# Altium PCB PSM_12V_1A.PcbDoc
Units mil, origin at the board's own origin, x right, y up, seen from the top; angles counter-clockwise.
Board outline 1600 x 1200 mil, 2 copper layers (Top Layer, Bottom Layer), stack 62 mil thick; 36 components, 17 nets, 77 pads, 9 vias.
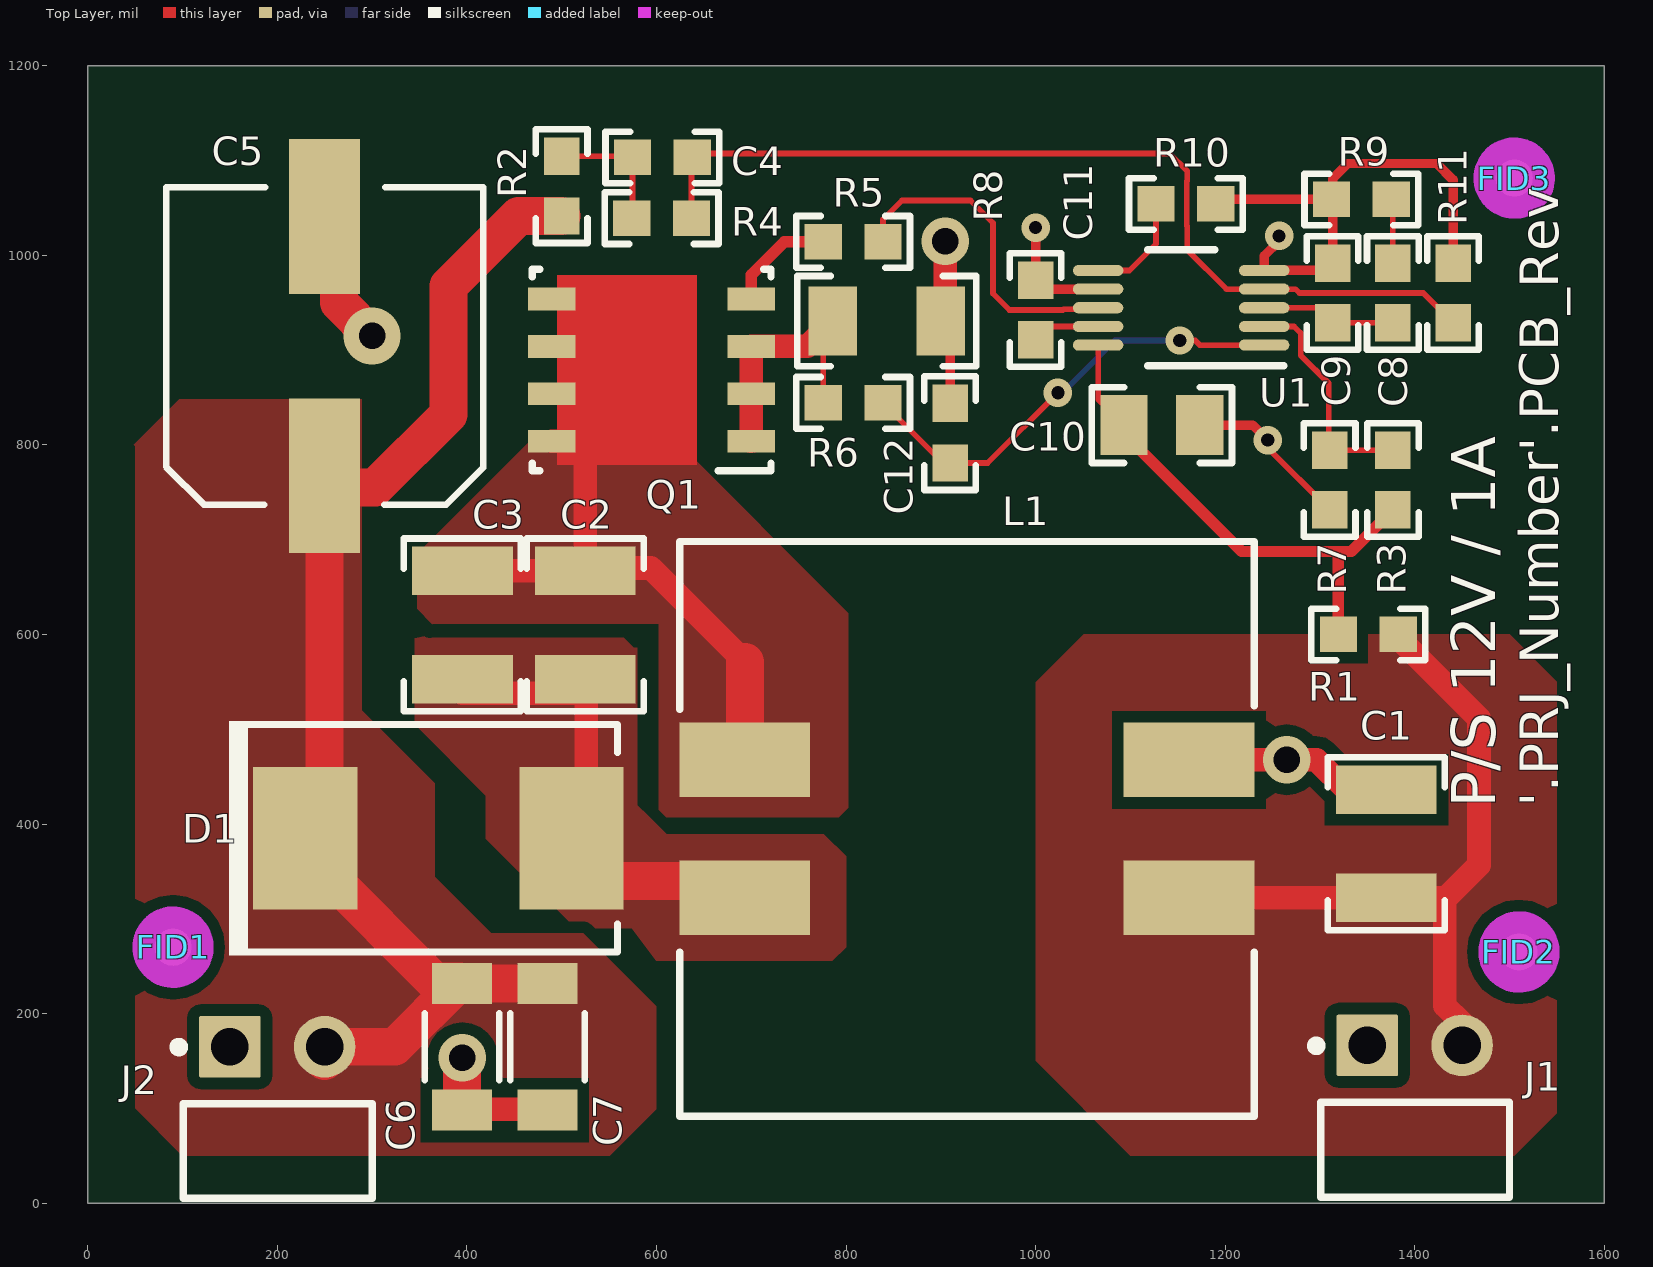
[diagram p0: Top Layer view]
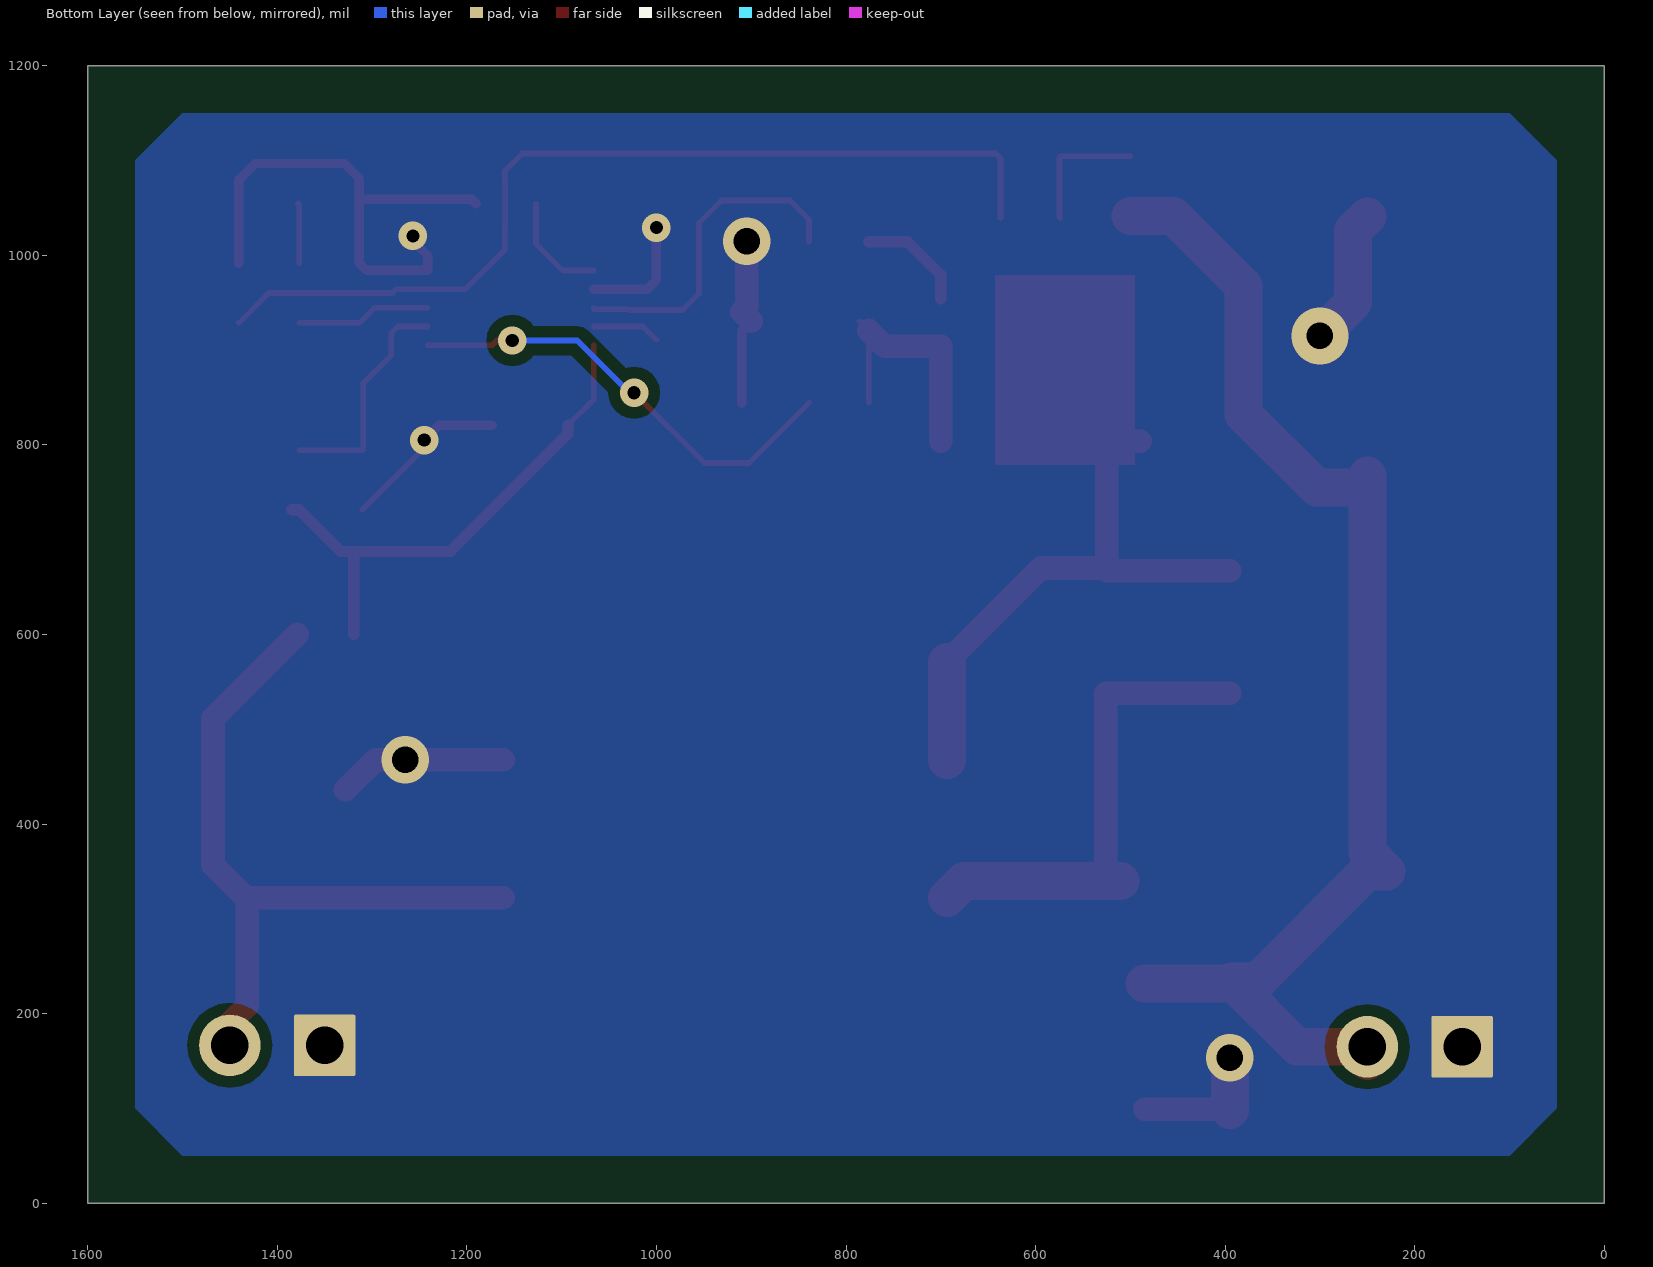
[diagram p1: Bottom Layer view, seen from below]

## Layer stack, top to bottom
Top Solder: solder mask 0.4, Solder Resist, Dk 3.5
Top Layer: signal copper 1.4
Dielectric1: core 59.2, FR-4, Dk 4.8
Bottom Layer: signal copper 1.4
Bottom Solder: solder mask 0.4, Solder Resist, Dk 3.5

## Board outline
0,0 0,1200 1600,1200 1600,0

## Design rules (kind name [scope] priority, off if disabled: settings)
AcuteAngle [All] p1: minimum=4.50000000000000E+0001 checktracksonly=FALSE
AssemblyTestPointUsage [All] p1: valid=2
BoardOutlineClearance BoardOutlineClearance_MountingHoles [OnCopper and InComponentClass('Mounting Holes')] p1: gap=39.37 ignorepadtopadclearanceinfootprint=FALSE
BoardOutlineClearance BoardOutlineClearance_Poly [OnCopper and IsPoly] p2: gap=25 ignorepadtopadclearanceinfootprint=FALSE
BoardOutlineClearance [OnCopper and Not InComponentClass('Logo') and not InComponentClass('FiducialMark') and not InRegion(1000,500,4000,800) and not InPoly] p3: gap=75 ignorepadtopadclearanceinfootprint=FALSE
Clearance Clearance_Keepouts [((IsTrack Or IsArc) And Not InPoly) And IsFree and IsKeepOut vs ((IsTrack Or IsArc) And Not InPoly) And IsFree and IsKeepOut] p1: gap=0 ignorepadtopadclearanceinfootprint=FALSE
Clearance Clearance_Poly [InPolygon] p2: gap=12 ignorepadtopadclearanceinfootprint=TRUE
Clearance Clearance_FiducialMark [IsKeepOut and InComponentClass('FiducialMark') vs IsPad and InComponentClass('FiducialMark')] p3: gap=0 ignorepadtopadclearanceinfootprint=FALSE
Clearance [All] p4: gap=7.87 ignorepadtopadclearanceinfootprint=TRUE
ComponentClearance ComponentClearance_MountingHoles_FiducialMarks [InComponentClass('Mounting Holes') vs InComponentClass('FiducialMark')] p1: gap=50 collisioncheckmode=3 verticalgap=10 showdistances=FALSE
ComponentClearance ComponentClearance_Shunt [InComponentClass('Header') vs InComponentClass('Shunt')] p2: gap=0 collisioncheckmode=3 verticalgap=0 showdistances=FALSE
ComponentClearance ComponentClearance_Logo [InComponentClass('Logo')] p3: gap=20 collisioncheckmode=3 verticalgap=10 showdistances=FALSE
ComponentClearance ComponentClearance_ScrewToNut [(HasFootprint('NY PMS 440 0025 PH')) vs (HasFootprint('Keystone_1902C'))] p4: gap=5 collisioncheckmode=3 verticalgap=10 showdistances=FALSE
ComponentClearance ComponentClearance_MountingHoles [InComponentClass('Mounting Holes')] p5: gap=250 collisioncheckmode=3 verticalgap=100000 showdistances=FALSE
ComponentClearance ComponentClearance_SmallPassives [HasFootprint('0201*') or HasFootprint('0402*') or HasFootprint('0508') or HasFootprint('0603*') or HasFootprint('0612') or HasFootprint('0805*') or HasFootprint('0815*') or HasFootprint('0830*') or HasFootprint('1206*') or HasFootprint('1210*') or HasFootprint('1808*') or HasFootprint('1812*') or HasFootprint('1825*') or HasFootprint('2010*') or HasFootprint('2220*') or HasFootprint('2225*') or HasFootprint('2512*') or HasFootprint('2728*') or HasFootprint('3518*') vs HasFootprint('0201*') or HasFootprint('0402*') or HasFootprint('0508') or HasFootprint('0603*') or HasFootprint('0612') or HasFootprint('0805*') or HasFootprint('0815*') or HasFootprint('0830*') or HasFootprint('1206*') or HasFootprint('1210*') or HasFootprint('1808*') or HasFootprint('1812*') or HasFootprint('1825*') or HasFootprint('2010*') or HasFootprint('2220*') or HasFootprint('2225*') or HasFootprint('2512*') or HasFootprint('2728*') or HasFootprint('3518*')] p6: gap=14.96 collisioncheckmode=3 verticalgap=10 showdistances=FALSE
ComponentClearance ComponentClearance_THtoSMT [IsThruComponent vs IsSMTComponent] p7: gap=40 collisioncheckmode=3 verticalgap=30 showdistances=FALSE
ComponentClearance ComponentClearance_THtoTH [IsThruComponent vs IsThruComponent] p8: gap=30 collisioncheckmode=3 verticalgap=30 showdistances=FALSE
ComponentClearance [All] p9: gap=30 collisioncheckmode=3 verticalgap=10 showdistances=FALSE
DiffPairsRouting [All] p1: maxlimit=100 minlimit=10 mostfreqgap=10 toplayer_minwidth=15 toplayer_maxwidth=15 toplayer_prefwidth=15 bottomlayer_minwidth=15 bottomlayer_maxwidth=15 bottomlayer_prefwidth=15 maxuncoupledlength=1000
FabricationTestPointUsage TestPointUsage [All] p1: valid=2 allowmultiple=FALSE
FabricationTestpoint Testpoint [All] p1: side=3 testpointundercomponent=TRUE minsize=40 maxsize=100 preferedsize=60 minholesize=0 maxholesize=40 preferedholesize=32 testpointgrid=1 allowsidetop=TRUE allowsidebottom=TRUE usegrid=TRUE gridtolerance=0.01
FanoutControl Fanout_LCC [IsLCC] p1: bgadir=Out bgaviamode=Centered fanoutstyle=Auto fanoutdirection=Alternating viagrid=1 // Fanout_LCC (Default Rule)
FanoutControl Fanout_BGA [IsBGA] p2: bgadir=Out bgaviamode=Centered fanoutstyle=Auto fanoutdirection=Alternating viagrid=1 // Fanout_BGA (Default Rule)
FanoutControl Fanout_Default [All] p4: bgadir=Out bgaviamode=Centered fanoutstyle=Auto fanoutdirection=Alternating viagrid=1 // Fanout_Default (Default Rule)
FanoutControl Fanout_Small [(CompPinCount < 5)] p5: bgadir=Out bgaviamode=Centered fanoutstyle=Auto fanoutdirection=OutThenIn viagrid=1 // Fanout_Small (Default Rule)
HoleSize [All] p1: absolutevalues=TRUE maxlimit=251 minlimit=7.87 maxpercent=80.000 minpercent=20.000
MinimumAnnularRing MinimumAnnularRing_ThermalPadVias [IsVia and InAnyComponent] p1: minimumring=5.91
MinimumAnnularRing [All] p2: minimumring=7.87
MinimumSolderMaskSliver MinimumSolderMaskSliver_Logo [InComponentClass('Logo') vs InComponentClass('Logo')] p1: minsoldermaskwidth=0.7
MinimumSolderMaskSliver [All] p2: minsoldermaskwidth=3.94
PlaneConnect [All] p1: planeconnectstyle=Relief reliefexpansion=10 reliefentries=4 reliefconductorwidth=10 reliefairgap=10
PolygonConnect [All] p1: connectstyle=Direct reliefconductorwidth=25 reliefentries=4 polygonreliefangle="90 Angle" airgapwidth=10
RoutingVias ThermalPadVias [IsVia and InAnyComponent] p1: holewidth=7.87 width=19.68 viastyle="Through Hole" minholewidth=7.87 minwidth=19.68 maxholewidth=12.99 maxwidth=23.62
RoutingVias [All] p2: holewidth=16 width=34 viastyle="Through Hole" minholewidth=7.87 minwidth=26 maxholewidth=40 maxwidth=65
SilkToBoardRegionClearance [Not ((IsComment or IsDesignator) And (Hide <> 'False')) and not InRegion(1000,500,4000,800)] p1:
SilkToSilkClearance SilkToSilkClearance_Pb-FreeLogo [(HasFootprint('Pb-Free_Overlay_Medium') OR HasFootprint('Pb-Free_Overlay_Small')) vs (HasFootprint('Pb-Free_Overlay_Medium') OR HasFootprint('Pb-Free_Overlay_Small'))] p1: silktosilkclearance=0
SilkToSilkClearance [All] p2: silktosilkclearance=3.94
SilkToSolderMaskClearance SilkToComponentPadClearance [(IsPad or IsFill or IsRegion) and InAnycomponent] p1: minsilkscreentomaskgap=5 clearancetoexposedcopper=TRUE
SilkToSolderMaskClearance "Silk to Solder Mask Opening" [All] p2: minsilkscreentomaskgap=3.94 clearancetoexposedcopper=FALSE
SolderMaskExpansion [All] p1: expansion=1.97
UnRoutedNet [All] p1: checkbadconnections=TRUE
Width [All] p1: maxlimit=100 minlimit=6 preferedwidth=10 checkconnectedcopper=TRUE
14 further rules are at their usual default settings.

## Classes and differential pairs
component class FiducialMark: FID1 FID2 FID3
component class AssemblyNote: ZZ1 ZZ2 ZZ3 ZZ4

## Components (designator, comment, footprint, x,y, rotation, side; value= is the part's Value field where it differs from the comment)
C1 "C3225X7S2A335M200AB" 1210 1370,379.12 r90 top value=3.3uF
C2 "C3225X7S2A335M200AB" 1210 524.85,609.98 r270 top value=3.3uF
C3 "C3225X7S2A335M200AB" 1210 395.27,609.98 r270 top value=3.3uF
C4 "C0603C474K8PACTU" 0603 606.27,1103.22 r0 top value=0.47uF
C5 "25SVPF180M" SVPF_E12 250,904.26 r90 top value=180uF
C6 "EMK316BB7226ML-T" 1206_190 394.8,165 r270 top value=22uF
C7 "EMK316BB7226ML-T" 1206_190 485,165 r270 top value=22uF
C8 "C1608X7R1C105K080AC" 0603 1376.97,960.17 r90 top value=1uF
C9 "C0603C474K8PACTU" 0603 1313.35,960.17 r90 top value=0.47uF
C10 "C2012X7R2A104K125AA" 0805_HV 1133.28,820.89 r0 top value=0.1uF
C11 "C1608X7R1C105K080AC" 0603 1000,942.26 r90 top value=1uF
C12 "C0603X102K5RACTU" 0603 909.84,812.39 r90 top value=1000pF
D1 "DIODE_SCHOTTKY" SMC 370,385 r0 top value=100V
FID1 "Fiducial" Fiducial10-20 90,270 r0 top
FID2 "Fiducial" Fiducial10-20 1510,265 r0 top
FID3 "Fiducial" Fiducial10-20 1505,1081.44 r0 top
J1 "TSW-102-08-G-S-RA" TSW-102-08-G-S-RA 1400,166.42 r0 top
J2 "TSW-102-08-G-S-RA" TSW-102-08-G-S-RA 200,165 r0 top
L1 "INDUCTOR_COUPLED_13_24" IND_MSD1583 927.61,394.87 r180 top value=47uH
Q1 "FDMS86101" TRANS_Fairchild_PQFN08A 594.88,878.89 r180 top value=100V
R1 "Resistor" 0603 1351,600 r0 top value=10
R2 "Resistor" 0603 500,1072.95 r270 top value=49.9
R3 "Resistor" 0603 1376.97,762.96 r270 top value=100k
R4 "Resistor" 0603 605.45,1039.16 r180 top value=49.9k
R5 "Resistor" 0603 807.48,1014.25 r180 top value=0
R6 "Resistor" 0603 807.48,844.26 r0 top value=221
R7 "Resistor" 0603 1310.34,762.96 r90 top value=33.2k
R8 "Resistor" 1206 842.91,930.44 r180 top value=0.01
R9 "Resistor" 0603 1343.67,1058.91 r0 top value=1.50k
R10 "Resistor" 0603 1158.5,1054.24 r180 top value=105k
R11 "Resistor" 0603 1440.47,960.17 r270 top value=5.90k
U1 "LM3481QMM/NOPB" DGS0010A_N 1153.6,944.59 r180 top
ZZ1 "This Assembly Note is for PCB labels only" AssemblyNoteLabel 181.93,1913 r0 top
ZZ2 "These assemblies are ESD sensitive, ESD precautions shall be observed." AssemblyNote 181.93,1804.11 r0 top
ZZ3 "These assemblies must be clean and free from flux and all contaminants. Use of no clean flux is not acceptable." AssemblyNote 181.93,1715.56 r0 top
ZZ4 "These assemblies must comply with workmanship standards IPC-A-610 Class 2, unless otherwise specified." AssemblyNote 181.93,1627 r0 top

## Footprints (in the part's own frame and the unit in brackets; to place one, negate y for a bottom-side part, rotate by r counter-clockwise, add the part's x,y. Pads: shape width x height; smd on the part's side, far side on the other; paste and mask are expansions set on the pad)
0603 [mm] "0603 from SM-752 data"
  rect 1x0.95 smd: 1(-0.8,0) 2(0.8,0)
  silkscreen extent -1.52,-0.69 1.52,0.69, body extent -0.87,-0.47 0.87,0.47, height 1
0805_HV [mil] "0805 with 30mil clearance between pads"
  rect 50x63 smd: 1(-40,0) 2(40,0)
  silkscreen extent -74,-40 74,40, body extent -43,-29 43,29, height 57
1206 [mm] "1206 from SM-752 data"
  rect 1.3x1.85 smd: 1(-1.45,0) 2(1.45,0)
  silkscreen extent -2.4,-1.21 2.4,1.21, body extent -1.7,-0.9 1.7,0.9, height 1.35
1206_190 [mm] "1206_190"
  rect 1.1x1.6 smd: 1(-1.7,0) 2(1.7,0)
  silkscreen extent -0.9,-1 0.9,1, body extent -1.75,-0.95 1.75,0.95, height 1.9
1210 [mm] "1210 from SM-752 data"
  rect 1.3x2.7 smd: 1(-1.45,0) 2(1.45,0)
  silkscreen extent -2.32,-1.57 2.32,1.57, body extent -1.7,-1.35 1.7,1.35, height 1.35
AssemblyNote [mil] "Assembly Note"
AssemblyNoteLabel [mil] "Assembly Note for PCB Labels"
DGS0010A_N [mm] "TSSOP, 10-Leads, Body 3x3mm, Pitch 0.5mm, IPC Medium Density"
  oval 1.35x0.3 smd: 1(-2.225,1) 2(-2.225,0.5) 3(-2.225,0) 4(-2.225,-0.5) 5(-2.225,-1) 6(2.225,-1) 7(2.225,-0.5) 8(2.225,0) 9(2.225,0.5) 10(2.225,1)
  silkscreen extent -2.75,-1.55 0.9,1.55, body extent -2.45,-1.5 2.45,1.5, height 0.96
Fiducial10-20 [mm]
  round 1 smd mask+0.5: 1(0,0)
  Top Layer keep-out circle w1.178: c0,0 r0.5
IND_MSD1583 [mm] "COILCRAFT"
  rect 3.5x2 smd: 1(-5.95,1.85) 2(-5.95,-1.85) 3(5.95,-1.85) 4(5.95,1.85)
  silkscreen extent -7.7,-7.7 7.7,7.7, body extent -7.55,-7.55 7.55,7.55, height 8.6
SMC [mil] "Molded Diode, 2-Leads, Body 6.9x5.8mm, IPC Medium Density, based on OnSemi component dimensions and land patterns"
  rect 110x150 smd: 1(-140.49,0) 2(140.49,0)
  silkscreen extent -221,-123 189,124, body extent -156,-116 156,116, height 91
SVPF_E12 [mm] "OS-CON  8x10"
  rect 4.15x1.9 smd: 1(-3.475,0) 2(3.475,0)
  silkscreen extent -4.25,-4.25 4.25,4.25, body extent -4.25,-4.25 4.25,4.25, height 12
TRANS_Fairchild_PQFN08A [mm] "Fairchild PQFN08A recommended land pattern"
  rect 1.27x0.61 smd: 1(-2.67,1.905) 2(-2.67,0.635) 3(-2.67,-0.635) 4(-2.67,-1.905) 5(2.67,-1.905) 6(2.67,-0.635) 7(2.67,0.635) 8(2.67,1.905)
  Top Layer region: -1.215,-2.55 2.535,-2.55 2.535,2.55 -1.215,2.55
  silkscreen extent -3.2,-2.7 3.2,2.7, body extent -3.05,-2.55 3.05,2.55, height 1.11
TSW-102-08-G-S-RA [mm] "Samtec Right Angle Header"
  rrect6% 1.65x1.65 hole 1: 1(-1.27,0)
  round 1.65 hole 1: 2(1.27,0)
  silkscreen extent -2.76,-4.06 2.54,0.11, body extent -2.54,-9.91 2.54,0.32, height 3.05

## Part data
C1 C2 C3: library part CMP-0009133-1, "CAP, CERM, 3.3 uF, 100 V, +/- 20%, X7S, 1210", Cap_Case=1210, Manufacturer=TDK, Supplier Part Number 1=445-5210-1-ND, TempCo=X7S, Tolerance_%=20%, Value1=Unknown, Value2=100V, ValueDisplayed=3.3uF
C4 C9: library part CMP-0006945-5, "CAP, CERM, 0.47 uF, 10 V, +/- 10%, X5R, 0603", Cap_Case=0603, Manufacturer=Kemet, Supplier Part Number 1=399-3114-1-ND, TempCo=X5R, Tolerance_%=10%, Value1=Unknown, Value2=10V, ValueDisplayed=0.47uF
C5: library part CMP-0012118-3, "CAP, Aluminum Polymer, 180 uF, 25 V, +/- 20%, 0.016 ohm, 2-Pin SMD, Body 8.3 x 8.3 mm, Height 12 mm SMD", Cap_Case=8.0x11.9, Manufacturer=Panasonic, Supplier Part Number 1=P16510CT-ND, Tolerance_%=20%, Value1="0.016 ohm", Value2=25V, ValueDisplayed=180uF
C6 C7: library part CMP-0008805-2, "CAP, CERM, 22 uF, 16 V, +/- 20%, X7R, 1206_190", Cap_Case=1206, Manufacturer="Taiyo Yuden", Supplier Part Number 1=587-4319-1-ND, TempCo=X7R, Tolerance_%=20%, Value1=Unknown, Value2=16V, ValueDisplayed=22uF
C8 C11: library part CMP-0007037-4, "CAP, CERM, 1 uF, 16 V, +/- 10%, X7R, 0603", Cap_Case=0603, Manufacturer=TDK, Supplier Part Number 1=445-1604-1-ND, TempCo=X7R, Tolerance_%=10%, Value1="0.0057 ohm", Value2=16V, ValueDisplayed=1uF
C10: library part CMP-0007886-2, "CAP, CERM, 0.1 uF, 100 V, +/- 10%, X7R, 0805", Cap_Case=0805, Manufacturer=TDK, Supplier Part Number 1=445-1418-1-ND, TempCo=X7R, Tolerance_%=10%, Value1="0.020726 ohm", Value2=100V, ValueDisplayed=0.1uF
C12: library part CMP-0006976-5, "CAP, CERM, 1000 pF, 50 V, +/- 10%, X7R, 0603", Cap_Case=0603, Manufacturer=Kemet, Supplier Part Number 1=399-5348-1-ND, TempCo=X7R, Tolerance_%=10%, Value1=Unknown, Value2=50V, ValueDisplayed=1000pF
D1: library part CMP-0028531-2, "Diode, Schottky, 100 V, 3 A, SMC", Manufacturer="ON Semiconductor", PartNumber=MBRS3100T3G, Value1=3A, Value2=0.62V
FID1 FID2 FID3: library part CMP-0077181-1, "Fiducial mark.  There is nothing to buy or mount.", Manufacturer=N/A
J1 J2: library part CMP-0055976-1, "Header, 100mil, 2x1, Gold, R/A, TH", Color=Black, Current_A=6.3A, Manufacturer=Samtec, Supplier Part Number 1=SAM1039-02-ND, Voltage_V=550V
L1: library part CMP-0076818-2, "Coupled inductor, 47 µH, 6.7 A, 0.1 ohm, SMD", Manufacturer=Coilcraft, PartNumber=MSD1583-473MEB, Supplier Part Number 1=994-MSD1583-473MEB, ValueDisplayed=47µH
Q1: library part CMP-0000984-1, "MOSFET, N-CH, 100 V, 60 A, PQFN08A", Alternate Manufacturer=None, Manufacturer="Fairchild Semiconductor", Supplier Part Number 1=FDMS86101CT-ND, Value2="39 nC"
R1: library part CMP-0025703-4, "RES, 10, 5%, 0.1 W, AEC-Q200 Grade 0, 0603", Manufacturer=Vishay-Dale, PartNumber=CRCW060310R0JNEA, Power_W=100mW, Supplier Part Number 1=541-10GCT-ND, TempCo="200 ppm/C", Tolerance_%=5%, Value2=0.1W, Value_Code=10R0, ValueDisplayed=10
R2: library part CMP-0022448-4, "RES, 49.9, 1%, 0.1 W, AEC-Q200 Grade 0, 0603", Manufacturer=Vishay-Dale, PartNumber=CRCW060349R9FKEA, Power_W=100mW, Supplier Part Number 1=541-49.9HCT-ND, TempCo="100 ppm/C", Tolerance_%=1%, Value2=0.1W, Value_Code=49R9, ValueDisplayed=49.9
R3: library part CMP-0021990-4, "RES, 100 k, 1%, 0.1 W, AEC-Q200 Grade 0, 0603", Manufacturer=Vishay-Dale, PartNumber=CRCW0603100KFKEA, Power_W=100mW, Supplier Part Number 1=541-100KHCT-ND, TempCo="100 ppm/C", Tolerance_%=1%, Value2=0.1W, Value_Code=100k
R4: library part CMP-0022447-4, "RES, 49.9 k, 1%, 0.1 W, AEC-Q200 Grade 0, 0603", Manufacturer=Vishay-Dale, PartNumber=CRCW060349K9FKEA, Power_W=100mW, Supplier Part Number 1=541-49.9KHCT-ND, TempCo="100 ppm/C", Tolerance_%=1%, Value2=0.1W, Value_Code=49k9, ValueDisplayed=49.9k
R5: library part CMP-0025697-4, "RES, 0, 5%, 0.1 W, AEC-Q200 Grade 0, 0603", Manufacturer=Vishay-Dale, PartNumber=CRCW06030000Z0EA, Power_W=100mW, Supplier Part Number 1=541-0.0GCT-ND, TempCo="200 ppm/C", Tolerance_%=5%, Value2=0.1W, Value_Code=0000, ValueDisplayed=0
R6: library part CMP-0022217-5, "RES, 221, 1%, 0.1 W, AEC-Q200 Grade 0, 0603", Manufacturer=Vishay-Dale, PartNumber=CRCW0603221RFKEA, Power_W=100mW, Supplier Part Number 1=541-221HCT-ND, TempCo="100 ppm/C", Tolerance_%=1%, Value2=0.1W, Value_Code=221R, ValueDisplayed=221
R7: library part CMP-0022339-4, "RES, 33.2 k, 1%, 0.1 W, AEC-Q200 Grade 0, 0603", Manufacturer=Vishay-Dale, PartNumber=CRCW060333K2FKEA, Power_W=100mW, Supplier Part Number 1=541-33.2KHCT-ND, TempCo="100 ppm/C", Tolerance_%=1%, Value2=0.1W, Value_Code=33k2, ValueDisplayed=33.2k
R8: library part CMP-0017256-2, "RES, 0.01, 1%, 0.5 W, 1206", Manufacturer="Stackpole Electronics Inc", PartNumber=CSR1206FK10L0, Power_W=500mW, Supplier Part Number 1=CSR1206FK10L0CT-ND, TempCo="100 ppm/C", Tolerance_%=1%, Value2=0.5W, Value_Code=R010, ValueDisplayed=0.01
R9: library part CMP-0022126-4, "RES, 1.50 k, 1%, 0.1 W, AEC-Q200 Grade 0, 0603", Manufacturer=Vishay-Dale, PartNumber=CRCW06031K50FKEA, Power_W=100mW, Supplier Part Number 1=541-1.50KHCT-ND, TempCo="100 ppm/C", Tolerance_%=1%, Value2=0.1W, Value_Code=1k50, ValueDisplayed=1.50k
R10: library part CMP-0021994-4, "RES, 105 k, 1%, 0.1 W, AEC-Q200 Grade 0, 0603", Manufacturer=Vishay-Dale, PartNumber=CRCW0603105KFKEA, Power_W=100mW, Supplier Part Number 1=541-105KHCT-ND, TempCo="100 ppm/C", Tolerance_%=1%, Value2=0.1W, Value_Code=105k
R11: library part CMP-0022515-4, "RES, 5.90 k, 1%, 0.1 W, AEC-Q200 Grade 0, 0603", Manufacturer=Vishay-Dale, PartNumber=CRCW06035K90FKEA, Power_W=100mW, Supplier Part Number 1=541-5.90KHCT-ND, TempCo="100 ppm/C", Tolerance_%=1%, Value2=0.1W, Value_Code=5k90, ValueDisplayed=5.90k
U1: library part CMP-0071928-2, "High Efficiency Low-Side N-Channel Controller for Switching Regulators, AEC-Q100 Grade 1, 10-pin Mini SOIC, 1000 Reel", Alternate Manufacturer="Texas Instruments", Alternate PartNumber=LM3481QMMX/NOPB
ZZ1: library part CMP-0003616-3
ZZ2: library part CMP-0077236-1
ZZ3: library part CMP-0077237-1
ZZ4: library part CMP-0077238-1

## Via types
v1: diameter 30, hole 14, Top Layer to Bottom Layer, 5 vias
v2: diameter 50, hole 28, Top Layer to Bottom Layer, 3 vias
v3: diameter 60, hole 28, Top Layer to Bottom Layer, 1 vias

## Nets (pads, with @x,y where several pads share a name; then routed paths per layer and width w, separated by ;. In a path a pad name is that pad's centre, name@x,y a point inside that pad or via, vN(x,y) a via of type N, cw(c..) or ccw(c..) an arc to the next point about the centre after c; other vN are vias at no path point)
GND: C1.2 C5.2 C6.2 C7.2 C9.2 C10.2 C11.2 C12.2 J1.1 J2.1 L1.2 R7.1 R8.1 R9.1 R10.1 R11.1 U1.5 U1.7 | length 1519.9
  Top Layer w6: v1(1245,805) 1245,796.81 R7.1
  Top Layer w10: R8.1 909.84,920.6 C12.2 ; v1@1000,1030 v1(1000,1029.24) C11.2 1009.48,964.28 U1.7 ; C10.2 1229.11,820.89 v1(1245,805) ; R10.1 1194.67,1058.91 R9.1 R9.1@1313.35,1057.73 ; v1(1256.87,1020.46) 1256.87,1015.15 1241.2,999.48 U1.5 1305.64,983.96 C9.2 R9.1@1313.35,1057.73 ; R11.1 1440.47,1079.6 1423.25,1096.83 1329.38,1096.83 1313.35,1080.8 R9.1@1313.35,1057.73
  Top Layer w25: C6.2@394.8,99.17 C7.2@484.8,99.17 ; R8.1 909.84,940.29 904.84,945.29 v2(904.84,1015) ; L1.2 v2(1265,467.7) 1296.44,467.7 C1.2@1327.93,436.21
  Top Layer w40: C5.2 265,1026.07 265,950 v3(300,915) ; C6.2 394.8,99.17 394.8,152.92 v2(395.27,153.39)
NetC1_1: C1.1 J1.2 L1.1 R1.2 | length 782.6
  Top Layer w25: L1.1 C1.1 1429.32,322.04 ; R1.2@1379.05,600 1467.74,511.31 1467.74,356.78 1432.99,322.04 1429.32,322.04 ; J1.2@1449.49,148.05 1449.49,190.51 1431.72,208.28 1431.72,319.63 1429.32,322.04
NetC2_1: C2.1 C3.1 L1.3 Q1.5 Q1.6 Q1.7 Q1.8 | length 614.1
  Top Layer w25: C3.1 C2.1 C2.1@524.85,670 ; Q1.8 524.85,803.89 C2.1@524.85,670 ; 693.35,570.73 594.09,670 C2.1@524.85,670
  Top Layer w40: L1.3 693.35,570.73
NetC2_2: C2.2 C3.2 D1.2 L1.4 | length 524.1
  Top Layer w25: C3.2@395.27,537.89 C2.2@524.85,537.89 ; D1.2@510.49,340 525.85,355.36 C2.2@525.85,537.89
  Top Layer w40: D1.2@510.49,340 675.39,340 L1.4
NetC4_1: C4.1 R2.1 R4.2 | length 139.7
  Top Layer w6: R2.1 573.55,1104.44 C4.1 574.77,1039.97 R4.2
NetC4_2: C4.2 R4.1 R11.2 U1.4 | length 992.1
  Top Layer w6: R4.1 636.95,1102.4 C4.2 641.94,1107.39 1141.45,1107.39 1160,1088.85 1160,1078.57 1159.44,1078.01 1159.44,1031.04 1160,1030.48 1160,1005.61 1201.34,964.28 U1.4 1274.29,964.28 1278.4,960.17 1408.98,960.17 R11.2
NetC8_1: C8.1 C9.1 U1.3 | length 142.4
  Top Layer w6: U1.3 1297.43,944.59 C9.1 C8.1
NetC8_2: C8.2 R9.2 | length 63.7
  Top Layer w6: C8.2 1376.97,1053.72 R9.2@1378.11,1054.87
NetC10_1: C10.1 R1.1 R3.2 U1.10 | length 553.6
  Top Layer w6: U1.10 1066,848.17 C10.1
  Top Layer w12: C10.1 1093.28,811.72 1217.5,687.5 1320,687.5 ; R1.1 1319.51,687.01 1320,687.5 ; R3.2@1384.74,731.47 R3.2 1333,687.5 1320,687.5
NetC11_1: C11.1 U1.9 | length 71.9
  Top Layer w6: C11.1 1014.15,924.91 U1.9
NetC12_1: C12.1 R6.2 U1.1 | length 484
  Top Layer w6: R6.2 902.35,780.89 C12.1 949.44,780.89 v1(1023.55,855) ; v1(1152.01,910.09) 1168.42,910.09 1173.28,905.22 U1.1
  Bottom Layer w6: v1(1023.55,855) 1028.4,855 1083.49,910.09 v1(1152.01,910.09)
NetQ1_1: Q1.1 Q1.2 Q1.3 R6.1 R8.2 | length 273.2
  Top Layer w6: R6.1 775.98,920.6 R8.2
  Top Layer w25: Q1.1 Q1.2 Q1.3 759.27,903.89 R8.2@775.98,920.6
NetQ1_4: Q1.4 R5.2 | length 115.9
  Top Layer w12: Q1.4 700,979.28 734.97,1014.25 R5.2
NetR3_1: R3.1 R7.2 U1.2 | length 244.2
  Top Layer w6: U1.2 1272.71,924.91 1279.66,917.96 1279.66,894.57 1309.23,865 1309.23,795.57 R7.2 R3.1
NetR5_1: R5.1 U1.8 | length 352
  Top Layer w6: R5.1 838.98,1037.7 859.01,1057.73 931.36,1057.73 955,1034.1 955,959.64 972.39,942.26 1028.54,942.26 1029.48,943.19 1066,943.19 U1.8
NetR10_2: R10.2 U1.6 | length 114.9
  Top Layer w6: U1.6 1098.96,983.96 1127.01,1012.01 R10.2
Vout: C5.1 C6.1 C7.1 D1.1 J2.2 R2.2 | length 1364.8
  Top Layer w40: J2.2@250,150 J2.2 323.94,165 C6.1@392.83,233.9 ; C5.1 C5.1@250,755 ; C7.1 C6.1 C6.1@392.83,233.9 ; R2.2 454.38,1041.45 380.51,967.58 380.51,832.18 303.34,755 C5.1@250,755 ; C5.1@250,755 250,370.31 229.51,349.81 250.19,349.81 366.1,233.9 C6.1@392.83,233.9
pads on no net: FID1.1 FID2.1 FID3.1

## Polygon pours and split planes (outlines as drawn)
GND on Bottom Layer "BOTTOM_LAYER_GND_P000" (solid, remove dead copper, pour order 0): 50,100 100,50 1500,50 1550,100 1550,1100 1500,1150 100,1150 50,1100
Vout on Top Layer "TOP_LAYER_VOUT_P008" (solid, remove dead copper, pour order 8): 288.85,847.95 96.73,847.95 48.78,800 50,798.78 50,100 100,50 550.83,50 600,99.17 600,207.98 522.98,285 425.59,285 366.1,344.49 366.1,442.74 288.85,519.99
NetC2_1 on Top Layer "TOP_LAYER_NETC2_1_P006" (solid, remove dead copper, pour order 6): 347.5,679.41 347.5,626.96 363.68,610.78 364.04,611.15 602.5,611.15 602.5,407.18 792.5,407.18 802.5,417.18 802.5,622.5 617.5,807.5 470,807.5 352.5,690
NetC2_2 on Top Layer "TOP_LAYER_NETC2_2_P004" (solid, remove dead copper, pour order 4): 345,598.47 345,505 420,430 420,384.68 514.68,290 573.79,290 600,255.68 785.68,255.68 800,270 800,365.75 776.69,389.06 610.94,389.06 580,420 580,585.75 576.11,585.75 563.39,598.47
NetC1_1 on Top Layer "TOP_LAYER_NETC1_1_P002" (solid, remove dead copper, pour order 2): 1505,50 1550,95 1550,550 1500,600 1050.6,600 999.96,549.36 999.96,150.03 1100,50

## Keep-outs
Keep-Out Layer:
  text ".Layer_Name" at 577,-858.49 h60

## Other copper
Top Layer:
  text ".Layer_Name" at 577,-858.49 h60
Bottom Layer:
  text ".Layer_Name" at 577,-858.49 h60

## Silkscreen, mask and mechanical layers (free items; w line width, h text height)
Top Overlay:
  text "'.PRJ_Number'.PCB_Rev" at 1565,418.33 h70 r90
  text "P/S 12V / 1A" at 1500,417.3 h80 r90
  text ".Layer_Name" at 577,-858.49 h60
Bottom Overlay:
  text ".Layer_Name" at 577,-858.49 h60
Top Paste:
  text ".Layer_Name" at 577,-858.49 h60
Bottom Paste:
  text ".Layer_Name" at 577,-858.49 h60
Top Solder:
  text ".Layer_Name" at 577,-858.49 h60
  text ".Layer_Name" at 577,-858.49 h60
Bottom Solder:
  text ".Layer_Name" at 577,-858.49 h60
Drill Guide:
  text ".Layer_Name" at 577,-858.49 h60
M1 Board Outline:
  the board outline again, w10
  text ".Layer_Name" at 577,-858.49 h60
M2 Board Dimensions:
  rectangle: 0,-275 125,-150
  rectangle: 125,-400 500,-275
  lines w7: 0,-275 1000,-275 ; 125,-400 125,-150 ; 250,-400 250,-150 ; 500,-400 500,-150 ; 750,-400 750,-150 ; 0,-400 1000,-400 1000,-150 0,-150 0,-400
  text ".Layer_Name" at 577,-858.49 h60
M3 3D STEP Top:
  text ".Layer_Name" at 577,-858.49 h60
M4 3D STEP Bottom:
  text ".Layer_Name" at 577,-858.49 h60
M5 Assembly Top:
  lines w10: -292,-930.17 6308,-930.17 ; -292,-726.83 6310,-726.83 ; -292,-523.5 -292,-1133.5 3713,-1133.5 6310,-1133.5 6310,-523.5 -291.5,-523.5 -291.5,-1133.5 1284,-1133.5 ; 2173,-1133.5 2173,-523.5 ; 3440,-726.83 3440,-523.5 ; 4280,-726.83 4280,-523.5 ; 4902,-1140 4902,-937.17
  text "COMPONENTS MARKED 'DNP' SHOULD NOT BE POPULATED." at 1153.5,-318.5 h60
  text "ASSEMBLY VARIANT:" at 1153,-434 h60
  text ".VariantName" at 2189,-434 h60
  text "PCB VIEWED FROM TOP SIDE" at -228.5,-655.67 h60
  text "BOARD #:" at 2248,-655.67 h60
  text ".PRJ_Number" at 2793.5,-655.67 h60
  text "REV:" at 3638,-655.67 h60
  text ".PCB_Rev" at 3929.5,-655.67 h60
  text "SVN REV:" at 4476,-655.67 h60
  text ".VersionControl_RevNumber" at 4982,-655.67 h60
  text "TID #:" at 2248,-859 h60
  text ".TID" at 2793.5,-859 h60
  text "PLOT NAME =" at -228.5,-1064.34 h60
  text ".plot_File_Name" at 577,-1064.34 h60
  text "GENERATED    :" at 2250,-1064.34 h60
  text ".Print_Date" at 3119.5,-1064.34 h60
  text ".Print_Time" at 3848.5,-1064.34 h60
  text "TEXAS INSTRUMENTS" at 5113,-1064.34 h60
M6 Assembly Bottom:
  lines w10: -292.5,-727.33 6309.5,-727.33 ; -290.5,-930.67 6309.5,-930.67 ; 1115.5,-1140.5 1115.5,-937.67 ; 1737.5,-727.33 1737.5,-524 ; 2577.5,-727.33 2577.5,-524 ; 3844.5,-1134 3844.5,-524 ; 4733.5,-1134 6309,-1134 6309,-524 -292.5,-524 -292.5,-1134 2304.5,-1134 6309.5,-1134 6309.5,-524
  text "COMPONENTS MARKED 'DNP' SHOULD NOT BE POPULATED." at 6102,-318 h60
  text ".VariantName" at 5058,-434 h60
  text "ASSEMBLY VARIANT:" at 6097,-434 h60
  text ".VersionControl_RevNumber" at 1035.5,-656.17 h60
  text "SVN REV:" at 1541.5,-656.17 h60
  text ".PCB_Rev" at 2088,-656.17 h60
  text "REV:" at 2379.5,-656.17 h60
  text ".PRJ_Number" at 3224,-656.17 h60
  text "BOARD #:" at 3769.5,-656.17 h60
  text "PCB VIEWED FROM BOTTOM SIDE" at 6246,-656.17 h60
  text ".TID" at 3224,-859.5 h60
  text "TID #:" at 3769.5,-859.5 h60
  text "TEXAS INSTRUMENTS" at 904.5,-1064.84 h60
  text ".Print_Time" at 2169,-1064.84 h60
  text ".Print_Date" at 2898,-1064.84 h60
  text "GENERATED    :" at 3767.5,-1064.84 h60
  text ".plot_File_Name" at 5440.5,-1064.84 h60
  text "PLOT NAME =" at 6246,-1064.84 h60
M9 Title Sheet:
  drawing of 57 lines, arcs and shapes, not listed
  text "1" at 739.84,8036.5 h70
  text "2" at 3235.5,8036.5 h70
  text "3" at 5724.84,8036.5 h70
  text "4" at 8231.51,8036.5 h70
  text "5" at 10730.5,8036.5 h70
  text "6" at 13235.5,8036.5 h70
  text "A" at -416.5,6893.5 h70
  text "A" at 14383.5,6893.5 h70
  text "B" at -416.5,4513.5 h70
  text "B" at 14383.5,4513.5 h70
  text "C" at -416.5,2138.5 h70
  text "C" at 14383.5,2138.5 h70
  text "PROJECT TITLE:" at 11343.5,277.5 h45
  text ".PRJ_Title" at 11393.5,144.17 h70
  text "DESIGNED FOR:" at 11343.5,-23.5 h45
  text ".PRJ_Customer" at 11393.5,-163.5 h70
  text "D" at -416.5,-231.5 h70
  text "D" at 14383.5,-231.5 h70
  text "FILE NAME:" at 11343.5,-323.5 h45
  text ".PCB_File_Name_No_Path" at 11393.5,-443.5 h70
  text "Texas Instruments (TI) and/or its licensors do not warrant the accuracy or completeness of this specification" at 6374,-605.34 h45
  text "ENGINEER:" at 11343.5,-613.5 h45
  text "LAYOUT BY:" at 12848.5,-613.5 h45
  text "or any information contained therein. TI and/or its licensors do not warrant that this design will meet" at 6329.01,-718 h45
  text ".PRJ_Engineer" at 11393.5,-768.49 h70
  text ".PCB_Layout" at 12899,-768.49 h70
  text "the specifications, will be suitable for your application or fit for any particular purpose, or will operate in" at 6329.01,-830.67 h45
  text ".Layer_Name" at 577,-858.49 h60
  text "ALTIUM DESIGNER VERSION:" at 12848.5,-923.5 h45
  text "an implementation. TI and/or its licensors do not warrant that the design is production worthy. You should" at 6329.01,-943.33 h45
  text "completely validate and test your design implementation to confirm the system functionality for your application." at 6374,-1056 h45
  text ".print_Scale" at 11393.5,-1056.83 h70
  text ".Application_BuildNumber" at 12899,-1056.83 h70
  text "1" at 739.84,-1263.5 h70
  text "2" at 3235.5,-1263.5 h70
  text "3" at 5724.84,-1263.5 h70
  text "4" at 8231.51,-1263.5 h70
  text "5" at 10730.5,-1263.5 h70
  text "6" at 13235.5,-1263.5 h70
M10 Fab Notes:
  drawing of 189 lines, arcs and shapes, not listed
  text "DESIGN INFORMATION" at 12382.02,6356.17 h60
  text "MIN. TRACK WIDTH:" at 11737.46,6224.05 h60
  text "8" at 12833.7,6224.05 h60
  text "MIL" at 12988.46,6224.05 h60
  text "MIN. CLEARANCE:" at 11737.46,6099.92 h60
  text "0.2" at 12773.7,6099.93 h60
  text "mm" at 12988.46,6099.92 h60
  text "MIN. VIA PAD SIZE:" at 11737.46,5975.8 h60
  text "24" at 12803.71,5975.8 h60
  text "MIL" at 12988.46,5975.8 h60
  text "0.05mm (2MIL)" at 12432.46,5845.9 h60
  text "MINIMUM ANNULAR RING" at 11408.23,5837.67 h60
  text "EXTERNAL" at 13140.46,5837.67 h60
  text "PER" at 11608.23,5727.55 h60
  text "IPC-D-275 CLASS 2 LEVEL C" at 11828.23,5727.54 h60
  text "MIL, HOLES" at 13316.46,5627.07 h60
  text "+/-" at 12924,5618.48 h60
  text "+/-" at 13778,5618.48 h60
  text "REGISTRATION TOLERANCES:" at 11408.23,5617.42 h60
  text "METAL" at 12608,5617.42 h60
  text "5" at 13184.2,5617.42 h60
  text "3" at 14017.2,5617.42 h60
  text "MIL" at 14133.46,5617.42 h60
  text "HOLE SIZE TOLERANCE (UNLESS OTHERWISE SPECIFIED):" at 11408.23,5519.1 h60
  text "+/-" at 13778,5516.23 h60
  text "3" at 14017.2,5515.17 h60
  text "MIL" at 14133.46,5515.17 h60
  text "MATERIAL:" at 11333.46,5377.52 h60
  text "FR-4 High Tg" at 12319.9,5249 h60
  text "X" at 12175.46,5241.01 h60
  text "FR-408" at 11754.46,5236.49 h60
  text "OTHER" at 13242.46,5236.49 h60
  text "62 MIL (1.6mm) +/-10%" at 12074.56,5093.46 h60
  text "X" at 11954.46,5091.01 h60
  text "THICKNESS:" at 11408.23,5085.24 h60
  text "OTHER" at 13359.46,5085.24 h60
  text "TOLERANCE:" at 11408.23,4946.92 h60
  text "X" at 12256.46,4946.92 h60
  text "ANSI IPC-6012 TYPE 3 CLASS 2" at 12434.48,4946.92 h60
  text "OTHER +/-" at 12434.46,4802.73 h60
  text "BOW & TWIST:" at 11408.23,4657.54 h60
  text "X" at 12256.46,4657.54 h60
  text "ANSI IPC-6012 TYPE 3 CLASS 2" at 12434.48,4657.54 h60
  text "OTHER +/-" at 12434.46,4510.85 h60
  text "DRILLING:" at 11333.46,4380.23 h60
  text "NC_DRILL FILES" at 13094.46,4275.04 h60
  text "REFERENCE:" at 11408.23,4271.1 h60
  text "X" at 12065.46,4271.01 h60
  text "AS SHOWN" at 12243.46,4271.1 h60
  text "X" at 12966.46,4271.1 h60
  text "OTHER" at 13392.46,4128.85 h60
  text "PTH COPPER THICKNESS:" at 11407.91,4125.32 h60
  text "X" at 12547.14,4125.32 h60
  text "20-30 um" at 12675.14,4125.32 h60
  text "BOARD FINISH:" at 11333.46,3977.73 h60
  text "SILKSCREEN:" at 11488.68,3867.6 h60
  text "X" at 12446.46,3867.6 h60
  text "TOP" at 12563.46,3867.6 h60
  text "BOTTOM" at 13074.46,3867.6 h60
  text "SILKSCREEN COLOR:" at 11488.68,3712.41 h60
  text "X" at 12445.46,3712.41 h60
  text "WHITE" at 12563.46,3712.41 h60
  text "OTHER" at 13074.46,3712.41 h60
  text "X" at 12576.46,3568.96 h60
  text "GREEN" at 12694.46,3568.96 h60
  text "OTHER" at 13312.46,3568.96 h60
  text "SOLDER RESIST COLOR:" at 11488.68,3562.1 h60
  text "X" at 12576.46,3414.71 h60
  text "MATTE" at 12694.46,3414.71 h60
  text "SEMI-GLOSS" at 13312,3414.07 h60
  text "IMMERSION GOLD (ENIG)" at 12394.46,3241.94 h60
  text "ENEPIG" at 13732,3234.72 h60
  text "SURFACE FINISH:" at 11333.46,3233.72 h60
  text "X" at 11515,3100 h60
  text "IMM. TIN/SILVER OR EQUIV" at 11663,3096.4 h60
  text "OTHER" at 13094.46,3092.47 h60
  text "ARRAY/PANEL:" at 11333.46,2937.09 h60
  text "CUT AND TRIM PER M1 BOARD OUTLINE" at 12394.46,2928.87 h60
  text "N.C. ROUTE" at 12394.46,2792.9 h60
  text "X" at 13082.46,2792.9 h60
  text "V. SCORE" at 13260.46,2792.9 h60
  text "CERTIFICATION:" at 11333.46,2663.77 h60
  text "MATERIALS AND WORKMANSHIP FOR ALL PCBS" at 12058.46,2663.77 h60
  text "TO MEET OR EXCEED THE REQUIREMENTS OF:" at 12058.46,2569.71 h60
  text "X" at 11695.97,2441.08 h60
  text "ANSI IPC-A-600F CLASS ->" at 11823.96,2441.08 h60
  text "X" at 13471.97,2441.08 h60
  text "2" at 13581.96,2441.08 h60
  text "1" at 13266.96,2439.58 h60
  text "3" at 13935.96,2439.58 h60
  text "X" at 12507.97,2293.39 h60
  text "RoHS" at 12635.96,2293.39 h60
  text "OTHER" at 13280.36,2293.39 h60
  text "PER ORDER" at 13677.42,2293.39 h60
  text "ALL BOARDS MUST MEET OR EXCEED UL94-V0 REQUIREMENTS." at 11361,2139.57 h60
  text "PCB MUST BEAR THE UL94V-0 UL REGISTERED MATERIAL ID NUMBER" at 11361,2023.5 h60
  text "ADDITIONAL REQUIREMENTS:" at 11333.46,1854.08 h60
  text "MICROSECTION:" at 11408.23,1746.95 h60
  text "YES" at 12313.96,1746.95 h60
  text "REQUIRED" at 13175.46,1602.62 h60
  text "BARE BOARD ELEC. TEST:" at 11408.23,1599.76 h60
  text "NONE" at 12713.96,1599.76 h60
  text "X" at 13057.46,1599.76 h60
  text "PER ORDER" at 13767.46,1599.76 h60
  text "XX MIL VIAS REQUIRE NON-CONDUCTIVE FILL AND PLANARIZE" at 11576.38,1394.82 h59
  text "XX MIL VIAS REQUIRE CONDUCTIVE FILL AND PLANARIZE" at 11584.38,1290.84 h60
  text "OUTER XX MIL TRACES REQUIRE 50 OHM SINGLE-ENDED IMPEDANCE" at 11583.39,1127.46 h58
  text "LAYER 2 & 3 (INNER LAYERS) XX MIL WIDE, XX MIL SPACE / TRACES REQUIRE 100 OHM DIFFERENTIAL IMPEDANCE" at 11575.39,891.74 h60
  text ".Layer_Name" at 577,-858.49 h60
M11 Gerber Information:
  lines w10: -292,-930.17 6308,-930.17 ; -292,-726.83 6310,-726.83 ; -292,-523.5 -292,-1133.5 3713,-1133.5 6310,-1133.5 6310,-523.5 -291.5,-523.5 -291.5,-1133.5 1284,-1133.5 ; 2173,-1133.5 2173,-523.5 ; 3440,-726.83 3440,-523.5 ; 4280,-726.83 4280,-523.5 ; 4902,-1140 4902,-937.17
  text "ALL ARTWORK VIEWED FROM TOP SIDE" at -228.5,-655.67 h60
  text "BOARD #:" at 2248,-655.67 h60
  text ".PRJ_Number" at 2793.5,-655.67 h60
  text "REV:" at 3638,-655.67 h60
  text ".PCB_Rev" at 3929.5,-655.67 h60
  text "SVN REV:" at 4476,-655.67 h60
  text ".VersionControl_RevNumber" at 4982,-655.67 h60
  text "LAYER NAME =" at -228.5,-858.49 h60
  text "TID #:" at 2248,-859 h60
  text ".TID" at 2793.5,-859 h60
  text "PLOT NAME =" at -228.5,-1064.34 h60
  text ".plot_File_Name" at 577,-1064.34 h60
  text "GENERATED    :" at 2250,-1064.34 h60
  text ".Print_Date" at 3119.5,-1064.34 h60
  text ".Print_Time" at 3848.5,-1064.34 h60
  text "TEXAS INSTRUMENTS" at 5113,-1064.34 h60
M12 Stackup:
  drawing of 191 lines, arcs and shapes, not listed
  text "Layer" at 9811.59,7672.44 h60
  text "Name" at 10221.51,7672.44 h60
  text "Material" at 11151.25,7672.44 h60
  text "Thickness" at 12011.02,7672.44 h60
  text "Constant" at 12660.85,7672.44 h60
  text "Board Layer Stack" at 13230.71,7672.44 h60
  text "1" at 9811.59,7552.44 h60
  text "Top Overlay" at 10221.51,7552.44 h60
  text "2" at 9811.59,7432.44 h60
  text "Top Solder" at 10221.51,7432.44 h60
  text "Solder Resist" at 11151.25,7432.44 h60
  text "0.40mil" at 12011.02,7432.44 h60
  text "3.5" at 12660.85,7432.44 h60
  text "3" at 9811.59,7312.44 h60
  text "Top Layer" at 10221.51,7312.44 h60
  text "Copper" at 11151.25,7312.44 h60
  text "1.40mil" at 12011.02,7312.44 h60
  text "4" at 9811.59,7192.44 h60
  text "Dielectric1" at 10221.51,7192.44 h60
  text "FR-4" at 11151.25,7192.44 h60
  text "59.20mil" at 12011.02,7192.44 h60
  text "4.8" at 12660.85,7192.44 h60
  text "5" at 9811.59,7072.44 h60
  text "Bottom Layer" at 10221.51,7072.44 h60
  text "Copper" at 11151.25,7072.44 h60
  text "1.40mil" at 12011.02,7072.44 h60
  text "6" at 9811.59,6952.44 h60
  text "Bottom Solder" at 10221.51,6952.44 h60
  text "Solder Resist" at 11151.25,6952.44 h60
  text "0.40mil" at 12011.02,6952.44 h60
  text "3.5" at 12660.85,6952.44 h60
  text "7" at 9811.59,6832.44 h60
  text "Bottom Overlay" at 10221.51,6832.44 h60
  text ".Layer_Name" at 577,-858.49 h60
M13 Component Bodies Top:
  text ".Layer_Name" at 577,-858.49 h60
M14 Component Bodies Bottom:
  text ".Layer_Name" at 577,-858.49 h60
M15 Courtyards Top:
  text ".Layer_Name" at 577,-858.49 h60
M16 Courtyards Bottom:
  text ".Layer_Name" at 577,-858.49 h60
Drill Drawing:
  circle w10: c2570.56,1052.28 r27.63
  lines w10: 2542.93,831.26 2598.18,831.26 2570.56,776.01 2542.93,831.26 ; 2542.93,900.33 2598.18,900.33 2598.18,955.58 2542.93,955.58 2542.93,900.33
  lines w12: 2492.84,738.71 5724.33,738.71 ; 2492.84,1111.67 5724.33,1111.67 ; 2830.7,614.39 2830.7,1235.99 ; 3162.7,614.39 3162.7,1235.99 ; 3799.27,614.39 3799.27,1235.99 ; 4058.41,614.39 4058.41,1235.99 ; 4433.57,614.39 4433.57,1235.99 ; 5157.9,614.39 5157.9,1235.99 ; 2492.84,614.39 5724.33,614.39 5724.33,1235.99 2492.84,1235.99 2492.84,614.39
  text "Symbol" at 2567.43,1148.97 h72
  text "Quantity" at 2868,1148.97 h72
  text "Finished Hole Size" at 3200,1148.97 h72
  text "Plated" at 3836.56,1148.97 h72
  text "Hole Type" at 4095.7,1148.97 h72
  text "Drill Layer Pair" at 4470.86,1148.97 h72
  text "Hole Tolerance" at 5195.19,1148.97 h72
  text "5" at 2868,1024.65 h60
  text "14.00mil (0.356mm)" at 3200,1024.65 h60
  text "PTH" at 3836.56,1024.65 h60
  text "Round" at 4095.7,1024.65 h60
  text "Top Layer - Bottom Layer" at 4470.86,1024.65 h60
  text "4" at 2868,900.33 h60
  text "28.00mil (0.711mm)" at 3200,900.33 h60
  text "PTH" at 3836.56,900.33 h60
  text "Round" at 4095.7,900.33 h60
  text "Top Layer - Bottom Layer" at 4470.86,900.33 h60
  text "4" at 2868,776.01 h60
  text "39.37mil (1.000mm)" at 3200,776.01 h60
  text "PTH" at 3836.56,776.01 h60
  text "Round" at 4095.7,776.01 h60
  text "Top Layer - Bottom Layer" at 4470.86,776.01 h60
  text "13 Total" at 2868,651.69 h60
  text ".Layer_Name" at 577,-858.49 h60
M17 Embedded Cavity:
  text ".Layer_Name" at 577,-858.49 h60
M18 Embedded Assembly:
  text ".Layer_Name" at 577,-858.49 h60
M19 Embedded Keepout:
  text ".Layer_Name" at 577,-858.49 h60

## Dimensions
0,-400 to 1000,-400 on M2 Board Dimensions
0,1200 to 1600,0 on M2 Board Dimensions
1600,0 to 0,1200 on M2 Board Dimensions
